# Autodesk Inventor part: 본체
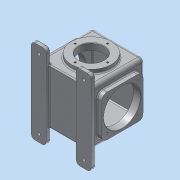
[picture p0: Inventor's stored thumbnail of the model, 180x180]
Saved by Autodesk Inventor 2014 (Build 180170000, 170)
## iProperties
Created: 2026-01
Part Number: 본체
Material: 알루미늄 6061
Document SubType Name: Modeling
Designer: dg
Density: 2.71 g/cm^3
Appearance: 알루미늄 - 평지
Mass: 2726.38 g
Surface Area: 2463.16 cm^2
Volume: 1006.05 cm^3
Author: dg
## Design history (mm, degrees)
sketch "스케치1"
  geometry: L1 (-74, 74)-(74, 74); L2 (74, 74)-(74, -74); L3 (74, -74)-(-74, -74); L4 (-74, -74)-(-74, 74); L5 (-74, 74)-(74, -74); L6 (74, 74)-(-74, -74); 1 further point
  constraints: 12 end point, 2 midpoint, 2 parallel, 1 horizontal, 1 perpendicular
  dimensions: "d0" = 148 distance of L1.end L2.end; "d1" = 148 distance between parallel lines of L4 L2
extrude "돌출1" new body sketch "스케치1" stored distance "d2" = 142; taper "d3" = 0 deg
fillet "모깎기1" dims "d4" = 10
fillet "모깎기2" dims "d5" = 10, "d72" = 3
feature "쉘1" dims "d6" = 7
sketch "스케치3"
  geometry: L1 (-56, -56)-(56, -56); L2 (56, -56)-(56, 56); L3 (56, 56)-(-56, 56); L4 (-56, 56)-(-56, -56); L5 (-56, -56)-(56, 56); L6 (56, -56)-(-56, 56); 1 further point
  constraints: 12 end point, 2 midpoint, 2 parallel, 1 horizontal, 1 perpendicular
  dimensions: "d10" = 112 distance of L3.end L2.end; "d11" = 112 distance of L2.end L1.end
extrude "돌출3" join sketch "스케치3" distance "d12" = 13; taper "d13" = 0 deg
sketch "스케치4"
  geometry: C1 r 50 at (0, 0); 1 further point
  constraints: 1 centre point, 1 coincident
  dimensions: "d14" = 100 diameter of C1
extrude "돌출4" cut sketch "스케치4" stored distance "d15" = 13; taper "d16" = 0 deg
sketch "스케치6"
  geometry: C1 r 50 at (0, 0) reference; 1 further point
  dimensions: "d31" = 41 horizontal distance of C1.centre point (-41, 41); "d32" = 41 horizontal distance of C1.centre point (-41, 41)
hole "구멍2" sketch "스케치6" at (-41, 41) diameter "d33" = 4.917; stored, may be unused: countersink angle "d37" = 90 deg, drill point angle "d39" = 118 deg; dims "d34" = 12, "d35" = 4, "d36" = 2, "d38" = 14
sketch "스케치7"
  geometry: L1 (81, -82)-(41, -82); L2 (41, -82)-(41, -70); L3 (41, -70)-(81, -70); L4 (81, -70)-(81, -82); L5 (-61, 74)-(61, 74) reference; 1 further point
  constraints: 8 end point, 2 parallel, 1 horizontal, 1 perpendicular
  dimensions: "d46" = 40 distance of L2.end L3.end; "d47" = 12 distance of L1.end L2.end; "d48" = 156 distance between parallel lines of L1 L5; "d49" = 81 distance from line of point (0, 0) L4
extrude "돌출6" join sketch "스케치7" stored distance "d50" = 228; taper "d51" = 0 deg
fillet "모깎기3" dims "d52" = 10
fillet "모깎기4" dims "d68" = 15
fillet "모깎기8" dims "d73" = 3
sketch "스케치9"
  geometry: 2 further points
  dimensions: "d74" = 94 vertical distance of point (20, -168) point (-41, -74); "d75" = 61 horizontal distance of point (20, -168) point (-41, -74)
hole "구멍4" sketch "스케치9" at (20, -168) diameter "d76" = 9; stored, may be unused: countersink angle "d80" = 90 deg, drill point angle "d82" = 118 deg; dims "d77" = 12, "d78" = 24, "d79" = 2, "d81" = 14
fillet "모깎기9" dims "d89" = 3
fillet "모깎기10" dims "d90" = 3
fillet "모깎기11" dims "d91" = 3
sketch "스케치10"
  geometry: 2 further points
  constraints: 1 coincident, 1 other
feature "엠보싱1" sketch "스케치10" dims "d0" = 148, "d1" = 148, "d10" = 112, "d11" = 112, "d92" = 0.5, "d93" = 0
sketch "스케치11"
  geometry: C1 r 54 at (61, -64); 1 further point
  constraints: 1 centre point, 1 coincident
  dimensions: "d94" = 108 diameter of C1
extrude "돌출7" join sketch "스케치11" distance "d95" = 11; taper "d96" = 0 deg
sketch "스케치12"
  geometry: C1 r 54 at (0, 0) reference; C2 r 34 at (0, 0); 1 further point
  constraints: 1 centre point, 1 coincident, 1 vertical alignment
  dimensions: "d97" = 68 diameter of C2; "d98" = 44 distance of C1.centre point (0, 44)
hole "구멍5" sketch "스케치12" diameter "d99" = 4.917; stored, may be unused: countersink angle "d103" = 90 deg, drill point angle "d105" = 118 deg; dims "d100" = 12, "d101" = 24, "d102" = 2, "d104" = 14
extrude "돌출8" cut sketch "스케치12" stored distance "d109" = 11; taper "d110" = 0 deg
chamfer "모따기1" distance "d111" = 1; stored, may be unused: second distance "d112" = 2, angle "d113" = 45 deg
fillet "모깎기12" dims "d114" = 3
node "솔리드1"
mirror "대칭1"
pattern_linear "직사각형 패턴1" dims "d42" = 82, "d45" = 82
mirror "대칭2"
mirror "대칭3"
pattern_linear "직사각형 패턴3" dims "d85" = 188, "d88" = 122
pattern_circular "원형 패턴2" dims angle "d107" = 360 deg
